(* Logix 5000 project; controller Electronic_Displays vendor 1 type 14 code 65 rev 17.4; software revision 17.01; part 9 of 9 *)
(* tags used below, declared in another part *)
   Address : STRING;   // "00" = all signs "01" = address 01 "02" = address 02 etc...(see protocol)
   FileLabel : STRING;   // "A" = default etc...(see protocol)
   Variable1Name : STRING;   // Name of variable Default is = U
   Variable2Name : STRING;   // Name of variable Default is = V
   ENVariable3Update : BOOL;   // 0 = don't update this variable 1 = update this variable
   Variable3Name : STRING;   // Name of variable Default is = W
   ENVariable4Update : BOOL;   // 0 = don't update this variable 1 = update this variable
   Variable4Name : STRING;   // Name of variable Default is = X
   EN : BOOL;   // Instruction Interface Enable Bit
   DN : BOOL;   // Instruction Interface Done Bit
   ER : BOOL;   // Instruction Interface Error Bit
   map_SignOutput : SINT[496];   // Ethernet/IP LEDSIGN.O Data I/O Mapping
   Packet1Sent : STRING;   // The actual packet sent to the sign (Packet1)
   Packet2Sent : STRING;   // The actual packet sent to the sign (Packet2)
   Packet3Sent : STRING;   // The actual packet sent to the sign (Packet3)
   InCycle : BOOL;   // Incycle
   Error : BOOL;   // Error
   Done : BOOL;   // Done
   SignETX : STRING;   // DO NOT EDIT = ^C
   SignSOH : STRING;   // DO NOT EDIT = ^A
   SignAddress : STRING;
   SignSTX : STRING;   // DO NOT EDIT = ^B
   SignVariable4Name : STRING;
   SignCommandCode : STRING;   // DO NOT EDIT = B
   SignVariable4Value : STRING;
   TotalPacketCount : DINT[7];   // Total Character Count
   Select : DINT;   // Packet Array Select
   PacketMax : DINT;   // Max Packet Count
   Packet3Offset : DINT;
   Packet2Offset : DINT;
   Packet1Offset : DINT;
   Packet : STRING[7];   // Packet Array to send to sign
(* UpdateSignVariables, continued *)

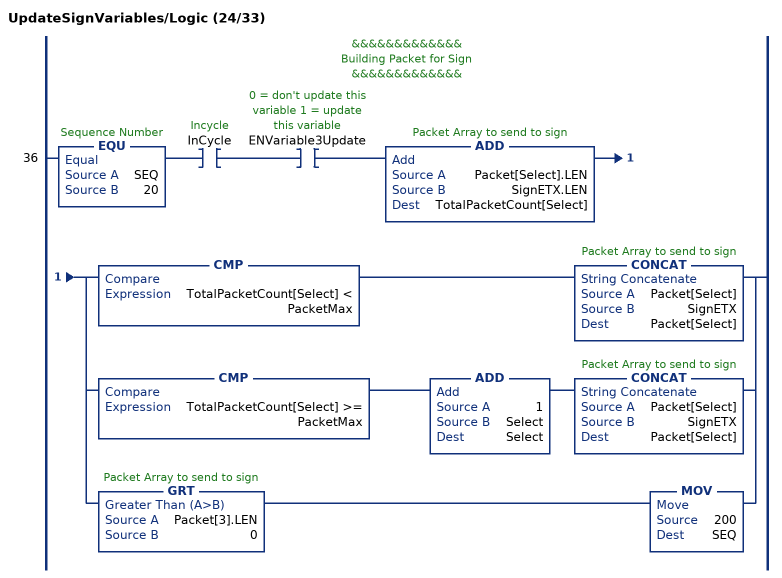
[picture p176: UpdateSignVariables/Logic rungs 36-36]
   // &&&&&&&&&&&&&
   // Building Packet for Sign
   // &&&&&&&&&&&&&
   36: EQU(SEQ,20)XIC(InCycle)XIC(ENVariable3Update)ADD(Packet[Select].LEN,SignETX.LEN,TotalPacketCount[Select])[CMP(TotalPacketCount[Select] < PacketMax) CONCAT(Packet[Select],SignETX,Packet[Select]) ,CMP(TotalPacketCount[Select] >= PacketMax) ADD(1,Select,Select) CONCAT(Packet[Select],SignETX,Packet[Select]) ,GRT(Packet[3].LEN,0) MOV(200,SEQ) ];
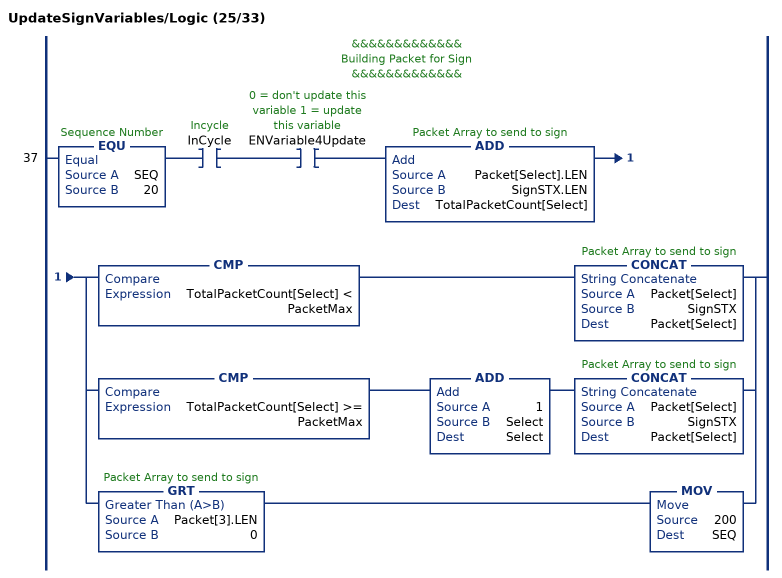
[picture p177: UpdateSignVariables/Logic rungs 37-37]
   // &&&&&&&&&&&&&
   // Building Packet for Sign
   // &&&&&&&&&&&&&
   37: EQU(SEQ,20)XIC(InCycle)XIC(ENVariable4Update)ADD(Packet[Select].LEN,SignSTX.LEN,TotalPacketCount[Select])[CMP(TotalPacketCount[Select] < PacketMax) CONCAT(Packet[Select],SignSTX,Packet[Select]) ,CMP(TotalPacketCount[Select] >= PacketMax) ADD(1,Select,Select) CONCAT(Packet[Select],SignSTX,Packet[Select]) ,GRT(Packet[3].LEN,0) MOV(200,SEQ) ];
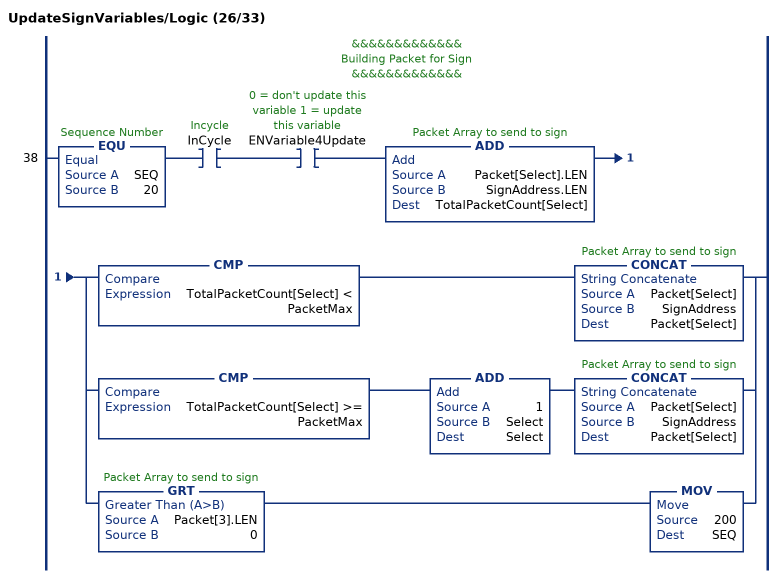
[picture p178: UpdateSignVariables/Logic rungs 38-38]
   // &&&&&&&&&&&&&
   // Building Packet for Sign
   // &&&&&&&&&&&&&
   38: EQU(SEQ,20)XIC(InCycle)XIC(ENVariable4Update)ADD(Packet[Select].LEN,SignAddress.LEN,TotalPacketCount[Select])[CMP(TotalPacketCount[Select] < PacketMax) CONCAT(Packet[Select],SignAddress,Packet[Select]) ,CMP(TotalPacketCount[Select] >= PacketMax) ADD(1,Select,Select) CONCAT(Packet[Select],SignAddress,Packet[Select]) ,GRT(Packet[3].LEN,0) MOV(200,SEQ) ];
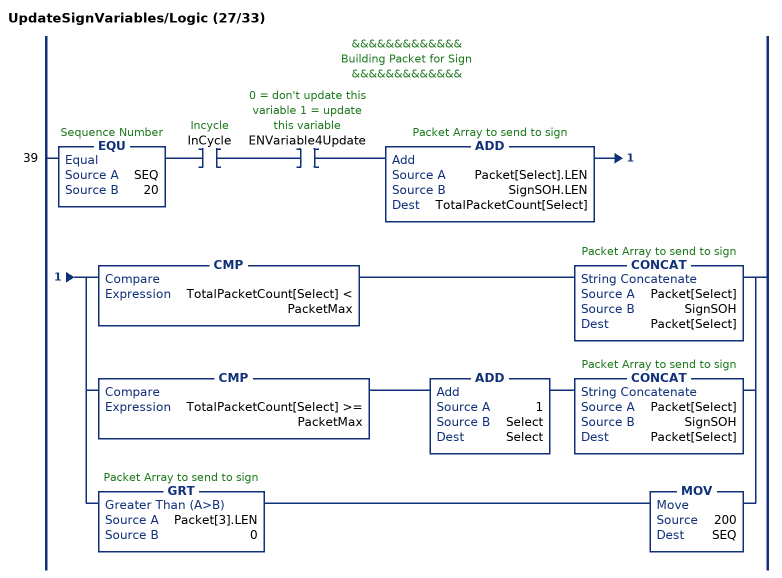
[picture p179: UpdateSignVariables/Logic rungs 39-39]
   // &&&&&&&&&&&&&
   // Building Packet for Sign
   // &&&&&&&&&&&&&
   39: EQU(SEQ,20)XIC(InCycle)XIC(ENVariable4Update)ADD(Packet[Select].LEN,SignSOH.LEN,TotalPacketCount[Select])[CMP(TotalPacketCount[Select] < PacketMax) CONCAT(Packet[Select],SignSOH,Packet[Select]) ,CMP(TotalPacketCount[Select] >= PacketMax) ADD(1,Select,Select) CONCAT(Packet[Select],SignSOH,Packet[Select]) ,GRT(Packet[3].LEN,0) MOV(200,SEQ) ];
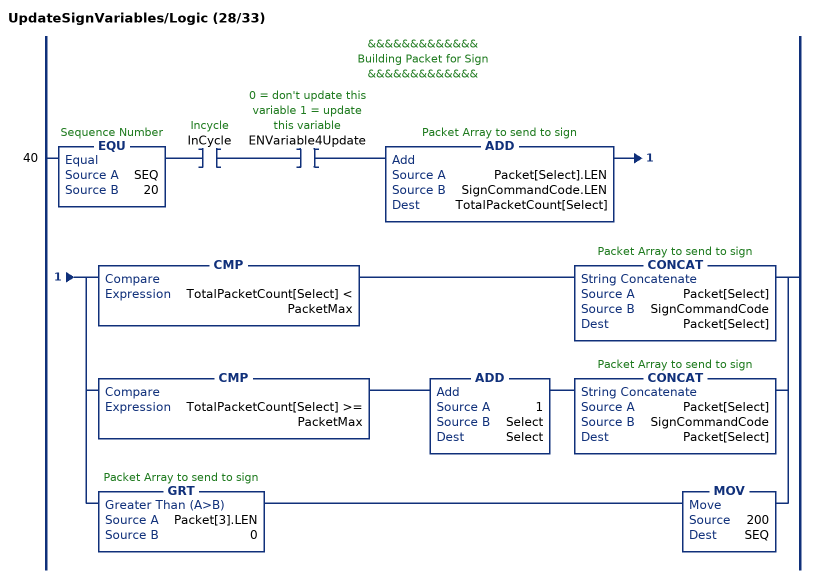
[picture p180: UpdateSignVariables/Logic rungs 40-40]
   // &&&&&&&&&&&&&
   // Building Packet for Sign
   // &&&&&&&&&&&&&
   40: EQU(SEQ,20)XIC(InCycle)XIC(ENVariable4Update)ADD(Packet[Select].LEN,SignCommandCode.LEN,TotalPacketCount[Select])[CMP(TotalPacketCount[Select] < PacketMax) CONCAT(Packet[Select],SignCommandCode,Packet[Select]) ,CMP(TotalPacketCount[Select] >= PacketMax) ADD(1,Select,Select) CONCAT(Packet[Select],SignCommandCode,Packet[Select]) ,GRT(Packet[3].LEN,0) MOV(200,SEQ) ];
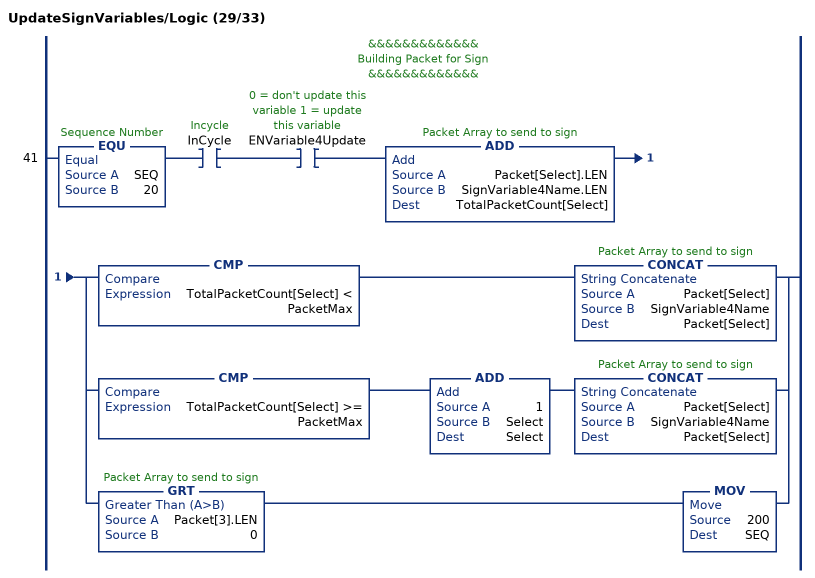
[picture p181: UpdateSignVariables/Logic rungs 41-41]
   // &&&&&&&&&&&&&
   // Building Packet for Sign
   // &&&&&&&&&&&&&
   41: EQU(SEQ,20)XIC(InCycle)XIC(ENVariable4Update)ADD(Packet[Select].LEN,SignVariable4Name.LEN,TotalPacketCount[Select])[CMP(TotalPacketCount[Select] < PacketMax) CONCAT(Packet[Select],SignVariable4Name,Packet[Select]) ,CMP(TotalPacketCount[Select] >= PacketMax) ADD(1,Select,Select) CONCAT(Packet[Select],SignVariable4Name,Packet[Select]) ,GRT(Packet[3].LEN,0) MOV(200,SEQ) ];
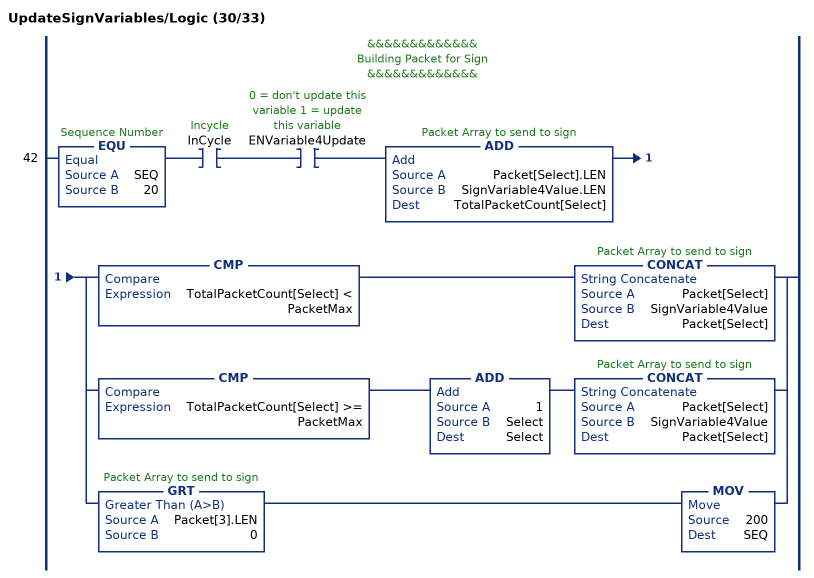
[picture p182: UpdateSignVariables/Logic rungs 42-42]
   // &&&&&&&&&&&&&
   // Building Packet for Sign
   // &&&&&&&&&&&&&
   42: EQU(SEQ,20)XIC(InCycle)XIC(ENVariable4Update)ADD(Packet[Select].LEN,SignVariable4Value.LEN,TotalPacketCount[Select])[CMP(TotalPacketCount[Select] < PacketMax) CONCAT(Packet[Select],SignVariable4Value,Packet[Select]) ,CMP(TotalPacketCount[Select] >= PacketMax) ADD(1,Select,Select) CONCAT(Packet[Select],SignVariable4Value,Packet[Select]) ,GRT(Packet[3].LEN,0) MOV(200,SEQ) ];
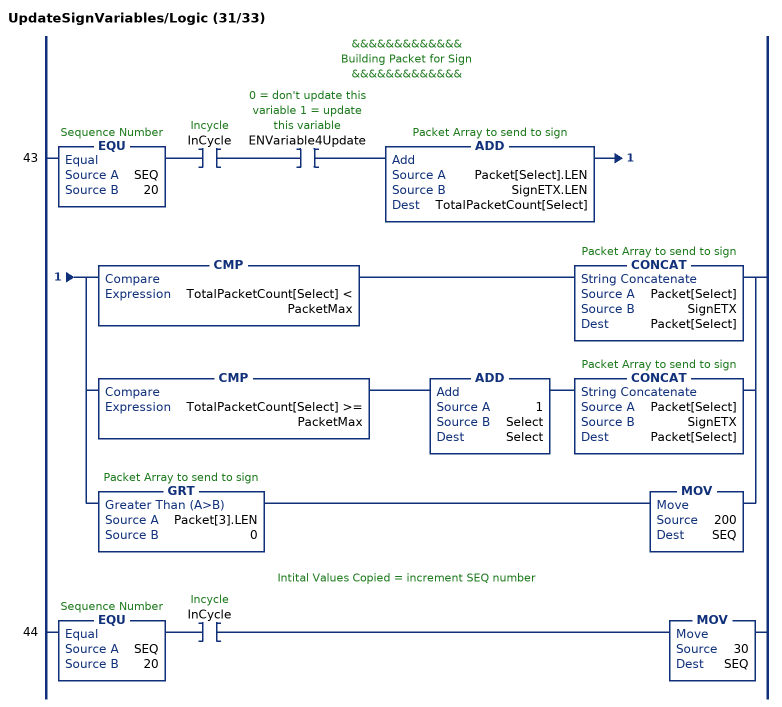
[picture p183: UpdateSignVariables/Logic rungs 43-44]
   // &&&&&&&&&&&&&
   // Building Packet for Sign
   // &&&&&&&&&&&&&
   43: EQU(SEQ,20)XIC(InCycle)XIC(ENVariable4Update)ADD(Packet[Select].LEN,SignETX.LEN,TotalPacketCount[Select])[CMP(TotalPacketCount[Select] < PacketMax) CONCAT(Packet[Select],SignETX,Packet[Select]) ,CMP(TotalPacketCount[Select] >= PacketMax) ADD(1,Select,Select) CONCAT(Packet[Select],SignETX,Packet[Select]) ,GRT(Packet[3].LEN,0) MOV(200,SEQ) ];
   // Intital Values Copied = increment SEQ number
   44: EQU(SEQ,20)XIC(InCycle)MOV(30,SEQ);
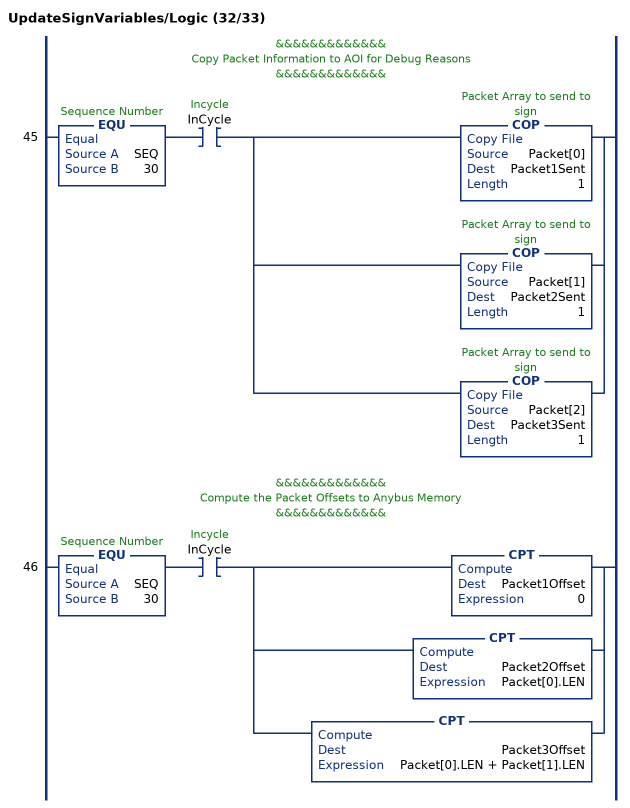
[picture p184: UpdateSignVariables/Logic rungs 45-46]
   // &&&&&&&&&&&&&
   // Copy Packet Information to AOI for Debug Reasons
   // &&&&&&&&&&&&&
   45: EQU(SEQ,30)XIC(InCycle)[COP(Packet[0],Packet1Sent,1) ,COP(Packet[1],Packet2Sent,1) ,COP(Packet[2],Packet3Sent,1) ];
   // &&&&&&&&&&&&&
   // Compute the Packet Offsets to Anybus Memory
   // &&&&&&&&&&&&&
   46: EQU(SEQ,30)XIC(InCycle)[CPT(Packet1Offset,0) ,CPT(Packet2Offset,Packet[0].LEN) ,CPT(Packet3Offset,Packet[0].LEN + Packet[1].LEN) ];
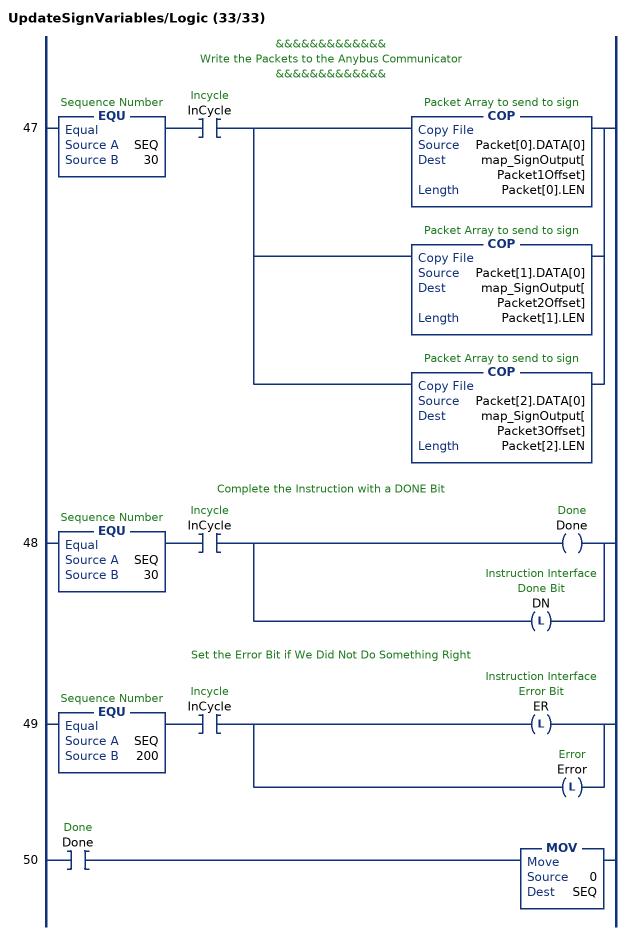
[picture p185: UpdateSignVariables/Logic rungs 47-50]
   // &&&&&&&&&&&&&
   // Write the Packets to the Anybus Communicator
   // &&&&&&&&&&&&&
   47: EQU(SEQ,30)XIC(InCycle)[COP(Packet[0].DATA[0],map_SignOutput[Packet1Offset],Packet[0].LEN) ,COP(Packet[1].DATA[0],map_SignOutput[Packet2Offset],Packet[1].LEN) ,COP(Packet[2].DATA[0],map_SignOutput[Packet3Offset],Packet[2].LEN) ];
   // Complete the Instruction with a DONE Bit
   48: EQU(SEQ,30)XIC(InCycle)[OTE(Done) ,OTL(DN) ];
   // Set the Error Bit if We Did Not Do Something Right
   49: EQU(SEQ,200)XIC(InCycle)[OTL(ER) ,OTL(Error) ];
   50: XIC(Done)MOV(0,SEQ);
END_ROUTINE
END_ADD_ON_INSTRUCTION

VAR_GLOBAL   (* controller tags *)
   E050_Scroller_TestMessage1 : AlphaScrollerSign;
   E050_Scroller_TestMessage2 : AlphaScrollerSign;
   E050_Static_TestMessage1 : AlphaStaticSign;
   E050_Static_TestMessage2 : AlphaStaticSign;
   ED050_Message1_Delay : TIMER := (PRE := 2000);
   ED050_Message2_Delay : TIMER := (PRE := 2000);
   ED050_Scroller_Config1 : ALPHASCROLL := (Address := '001', TextMessage := '123456789', PacketSent := '$04$07001$0A01123456789$12');
   ED050_Scroller_Config2 : ALPHASCROLL := (Address := '001', TextMessage := 'ABCDEFGH', PacketSent := '$04$07001$0A01ABCDEFGH$12');
   ED050_Scroller_Message1_Delay : TIMER := (PRE := 2000);
   ED050_Scroller_Message2_Delay : TIMER := (PRE := 2000);
   ED050_Static_Config1 : ALPHASTATIC := (Address := '00', TextMessage := '12345678', PacketSent := '$020012345678$03');
   ED050_Static_Config2 : ALPHASTATIC := (Address := '00', TextMessage := 'ABCDEFGH', PacketSent := '$0200ABCDEFGH$03');
   ED050_Static_Message1_Delay : TIMER := (PRE := 2000);
   ED050_Static_Message2_Delay : TIMER := (PRE := 2000);
   ED202_Config1 : NUMSIGN := (Address := '01', NumberValue := 123, PacketSent := '$0201123$03');
   ED202_Config2 : NUMSIGN := (Address := '01', NumberValue := 456, PacketSent := '$0201456$03');
   ED202_Message1_Delay : TIMER := (PRE := 2000);
   ED202_Message2_Delay : TIMER := (PRE := 2000);
   ED202_TestMessage1 : NumberSign;
   ED202_TestMessage2 : NumberSign := (EN := 1, DN := 1);
   EDV : LEDSIGN := (Address := '00', CommandCode := 'A', FileLabel := 'A', Text1Message := 'EDV Test #1', Text2Message := 'EDV Test #2', TextFont := '1', TextColor := '1', TextAlign := 'M', TextAttribute := '0', TextEffect := 'H', TextSpeed := '3', TextPause := '00', Packet1Sent := '^B00^AAA^GMH^H0^F1^O1^H0EDV Test #2^C');
   EDV_Message1_Delay : TIMER := (PRE := 5000);
   EDV_Message2_Delay : TIMER := (PRE := 2000);
   EDV_TestMessage1 : SendSignMessage := (ENText1Message := 1);
   EDV_TestMessage2 : SendSignMessage := (ENText2Message := 1, ENTextFormats := 1);
   ENABLE : DINT := 8;
   SEQ : DINT := 40;
END_VAR

PROGRAM MainProgram   (* main routine MainRoutine *)

ROUTINE MainRoutine   (* ladder *)
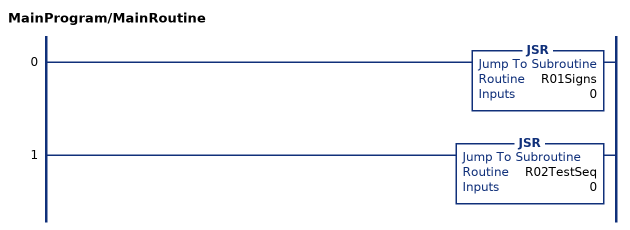
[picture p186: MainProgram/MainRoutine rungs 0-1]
   0: JSR(R01Signs,0);
   1: JSR(R02TestSeq,0);
END_ROUTINE

ROUTINE R01Signs   (* ladder *)
// Test Routines
// for Signs
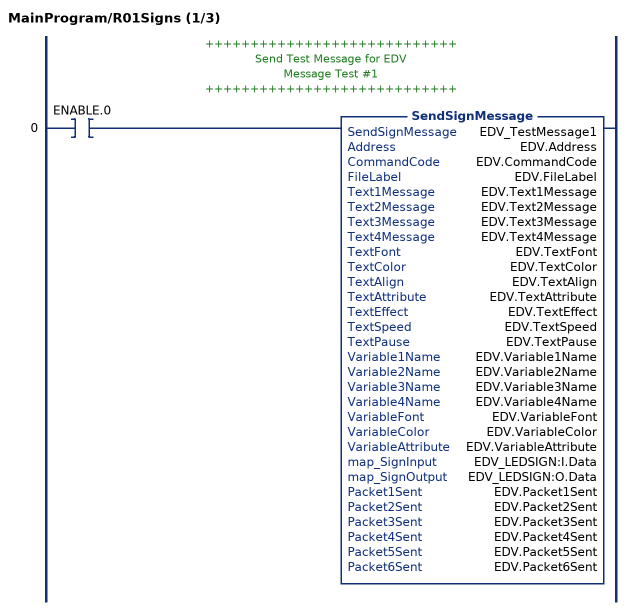
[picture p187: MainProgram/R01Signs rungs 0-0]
   // ++++++++++++++++++++++++++++
   // Send Test Message for EDV
   // Message Test #1
   // ++++++++++++++++++++++++++++
   0: XIC(ENABLE.0)SendSignMessage(EDV_TestMessage1,EDV.Address,EDV.CommandCode,EDV.FileLabel,EDV.Text1Message,EDV.Text2Message,EDV.Text3Message,EDV.Text4Message,EDV.TextFont,EDV.TextColor,EDV.TextAlign,EDV.TextAttribute,EDV.TextEffect,EDV.TextSpeed,EDV.TextPause,EDV.Variable1Name,EDV.Variable2Name,EDV.Variable3Name,EDV.Variable4Name,EDV.VariableFont,EDV.VariableColor,EDV.VariableAttribute,EDV_LEDSIGN:I.Data,EDV_LEDSIGN:O.Data,EDV.Packet1Sent,EDV.Packet2Sent,EDV.Packet3Sent,EDV.Packet4Sent,EDV.Packet5Sent,EDV.Packet6Sent);
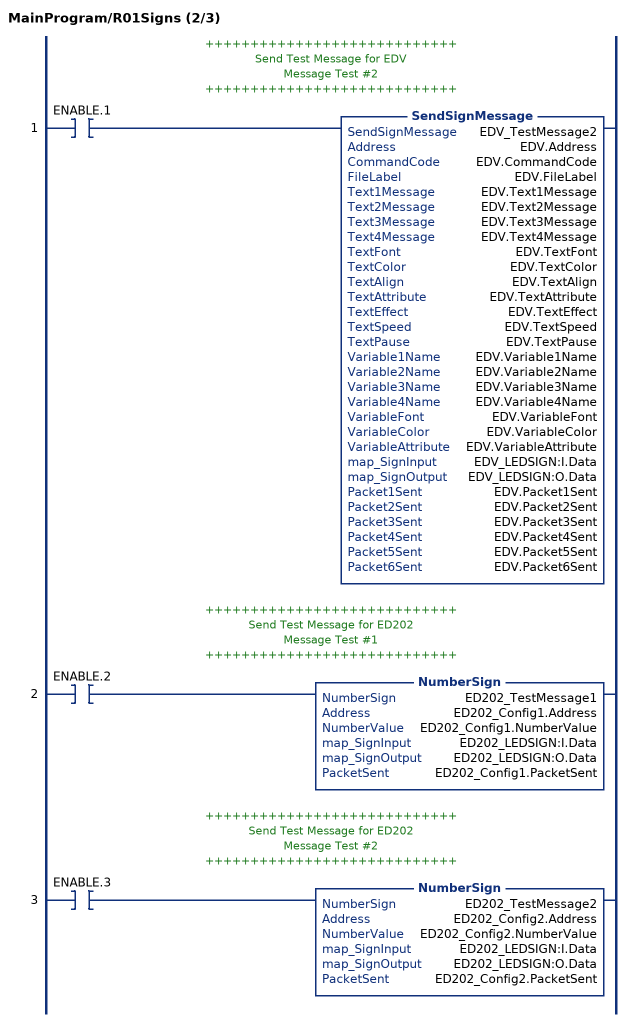
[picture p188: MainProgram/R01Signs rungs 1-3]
   // ++++++++++++++++++++++++++++
   // Send Test Message for EDV
   // Message Test #2
   // ++++++++++++++++++++++++++++
   1: XIC(ENABLE.1)SendSignMessage(EDV_TestMessage2,EDV.Address,EDV.CommandCode,EDV.FileLabel,EDV.Text1Message,EDV.Text2Message,EDV.Text3Message,EDV.Text4Message,EDV.TextFont,EDV.TextColor,EDV.TextAlign,EDV.TextAttribute,EDV.TextEffect,EDV.TextSpeed,EDV.TextPause,EDV.Variable1Name,EDV.Variable2Name,EDV.Variable3Name,EDV.Variable4Name,EDV.VariableFont,EDV.VariableColor,EDV.VariableAttribute,EDV_LEDSIGN:I.Data,EDV_LEDSIGN:O.Data,EDV.Packet1Sent,EDV.Packet2Sent,EDV.Packet3Sent,EDV.Packet4Sent,EDV.Packet5Sent,EDV.Packet6Sent);
   // ++++++++++++++++++++++++++++
   // Send Test Message for ED202
   // Message Test #1
   // ++++++++++++++++++++++++++++
   2: XIC(ENABLE.2)NumberSign(ED202_TestMessage1,ED202_Config1.Address,ED202_Config1.NumberValue,ED202_LEDSIGN:I.Data,ED202_LEDSIGN:O.Data,ED202_Config1.PacketSent);
   // ++++++++++++++++++++++++++++
   // Send Test Message for ED202
   // Message Test #2
   // ++++++++++++++++++++++++++++
   3: XIC(ENABLE.3)NumberSign(ED202_TestMessage2,ED202_Config2.Address,ED202_Config2.NumberValue,ED202_LEDSIGN:I.Data,ED202_LEDSIGN:O.Data,ED202_Config2.PacketSent);
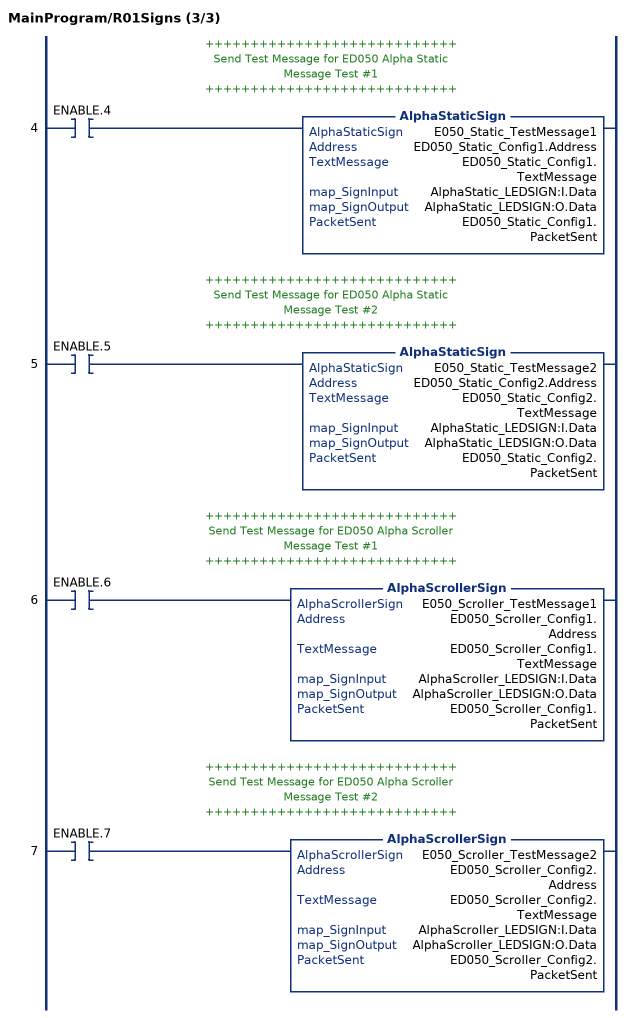
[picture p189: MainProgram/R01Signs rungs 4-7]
   // ++++++++++++++++++++++++++++
   // Send Test Message for ED050 Alpha Static
   // Message Test #1
   // ++++++++++++++++++++++++++++
   4: XIC(ENABLE.4)AlphaStaticSign(E050_Static_TestMessage1,ED050_Static_Config1.Address,ED050_Static_Config1.TextMessage,AlphaStatic_LEDSIGN:I.Data,AlphaStatic_LEDSIGN:O.Data,ED050_Static_Config1.PacketSent);
   // ++++++++++++++++++++++++++++
   // Send Test Message for ED050 Alpha Static
   // Message Test #2
   // ++++++++++++++++++++++++++++
   5: XIC(ENABLE.5)AlphaStaticSign(E050_Static_TestMessage2,ED050_Static_Config2.Address,ED050_Static_Config2.TextMessage,AlphaStatic_LEDSIGN:I.Data,AlphaStatic_LEDSIGN:O.Data,ED050_Static_Config2.PacketSent);
   // ++++++++++++++++++++++++++++
   // Send Test Message for ED050 Alpha Scroller
   // Message Test #1
   // ++++++++++++++++++++++++++++
   6: XIC(ENABLE.6)AlphaScrollerSign(E050_Scroller_TestMessage1,ED050_Scroller_Config1.Address,ED050_Scroller_Config1.TextMessage,AlphaScroller_LEDSIGN:I.Data,AlphaScroller_LEDSIGN:O.Data,ED050_Scroller_Config1.PacketSent);
   // ++++++++++++++++++++++++++++
   // Send Test Message for ED050 Alpha Scroller
   // Message Test #2
   // ++++++++++++++++++++++++++++
   7: XIC(ENABLE.7)AlphaScrollerSign(E050_Scroller_TestMessage2,ED050_Scroller_Config2.Address,ED050_Scroller_Config2.TextMessage,AlphaScroller_LEDSIGN:I.Data,AlphaScroller_LEDSIGN:O.Data,ED050_Scroller_Config2.PacketSent);
END_ROUTINE

ROUTINE R02TestSeq   (* ladder *)
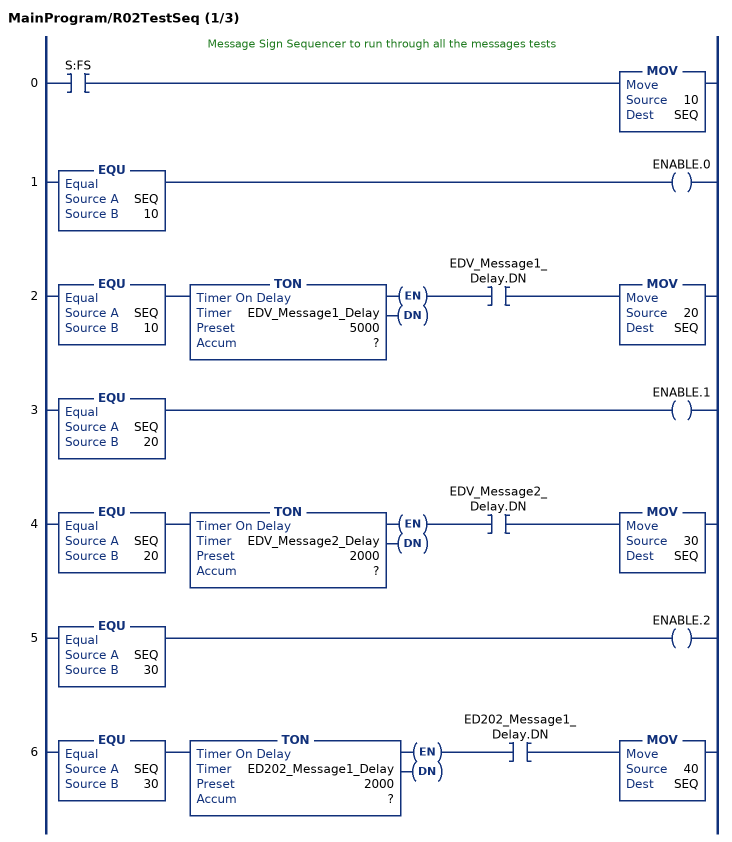
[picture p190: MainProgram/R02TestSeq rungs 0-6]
   // Message Sign Sequencer to run through all the messages tests
   0: XIC(S:FS)MOV(10,SEQ);
   1: EQU(SEQ,10)OTE(ENABLE.0);
   2: EQU(SEQ,10)TON(EDV_Message1_Delay,?,?)XIC(EDV_Message1_Delay.DN)MOV(20,SEQ);
   3: EQU(SEQ,20)OTE(ENABLE.1);
   4: EQU(SEQ,20)TON(EDV_Message2_Delay,?,?)XIC(EDV_Message2_Delay.DN)MOV(30,SEQ);
   5: EQU(SEQ,30)OTE(ENABLE.2);
   6: EQU(SEQ,30)TON(ED202_Message1_Delay,?,?)XIC(ED202_Message1_Delay.DN)MOV(40,SEQ);
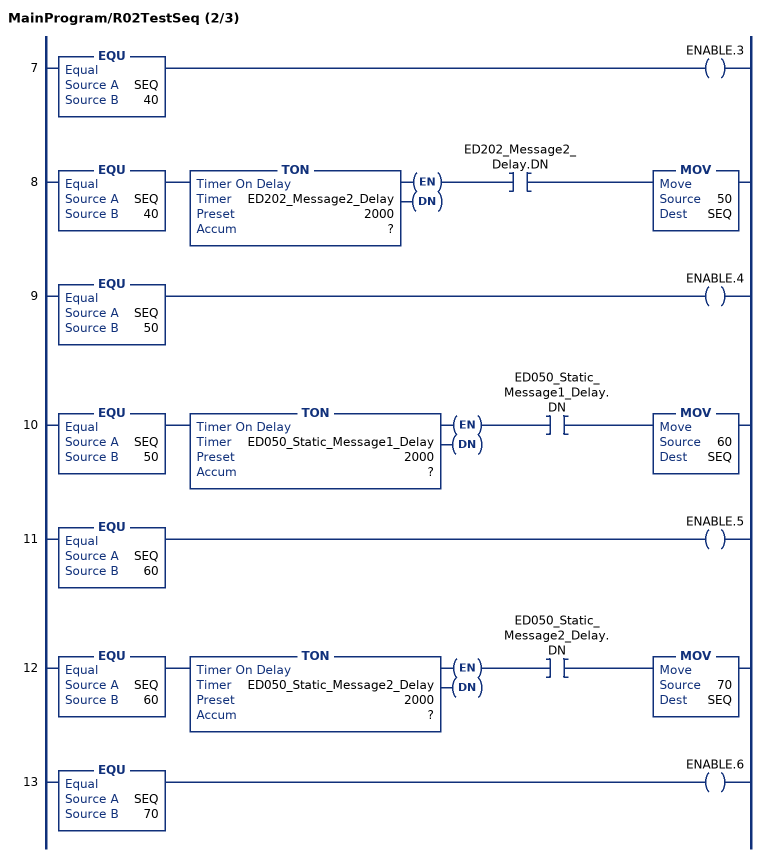
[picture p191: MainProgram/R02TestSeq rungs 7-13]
   7: EQU(SEQ,40)OTE(ENABLE.3);
   8: EQU(SEQ,40)TON(ED202_Message2_Delay,?,?)XIC(ED202_Message2_Delay.DN)MOV(50,SEQ);
   9: EQU(SEQ,50)OTE(ENABLE.4);
   10: EQU(SEQ,50)TON(ED050_Static_Message1_Delay,?,?)XIC(ED050_Static_Message1_Delay.DN)MOV(60,SEQ);
   11: EQU(SEQ,60)OTE(ENABLE.5);
   12: EQU(SEQ,60)TON(ED050_Static_Message2_Delay,?,?)XIC(ED050_Static_Message2_Delay.DN)MOV(70,SEQ);
   13: EQU(SEQ,70)OTE(ENABLE.6);
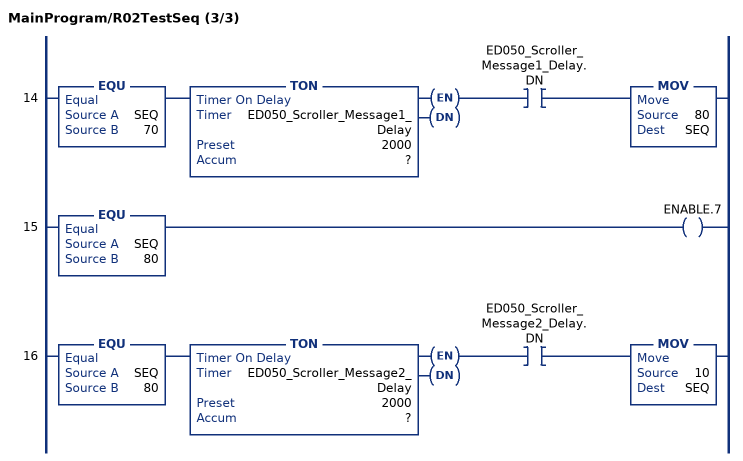
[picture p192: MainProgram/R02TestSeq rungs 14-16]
   14: EQU(SEQ,70)TON(ED050_Scroller_Message1_Delay,?,?)XIC(ED050_Scroller_Message1_Delay.DN)MOV(80,SEQ);
   15: EQU(SEQ,80)OTE(ENABLE.7);
   16: EQU(SEQ,80)TON(ED050_Scroller_Message2_Delay,?,?)XIC(ED050_Scroller_Message2_Delay.DN)MOV(10,SEQ);
END_ROUTINE
END_PROGRAM
